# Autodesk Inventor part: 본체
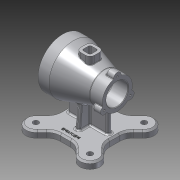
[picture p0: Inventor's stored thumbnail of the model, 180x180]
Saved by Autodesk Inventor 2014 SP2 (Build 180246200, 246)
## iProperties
Created: 2018-03
Part Number: 본체
Material: 알루미늄 6061
Document SubType Name: Modeling
Designer: 거성
Density: 2.71 g/cm^3
Appearance: 알루미늄 - 평지
Mass: 1030.73 g
Surface Area: 859.626 cm^2
Volume: 380.342 cm^3
Author: 거성
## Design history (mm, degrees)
sketch "스케치1"
  geometry: L1 (-50, 0)-(50, 0); L2 (-50, 36)-(-50, 45); L3 (-50, 45)-(-30, 45); L4 (-30, 45)-(27, 27.5); L5 (50, 27.5)-(50, 21); L6 (49, 20)-(23, 20); L7 (20, 23)-(20, 23); L8 (17, 26)-(-24, 26); L9 (-27, 29)-(-27, 32); L10 (-30, 35)-(-49, 35); L11 (27, 27.5)-(50, 27.5); L12 (-50, 36)-(-49, 35); L13 (49, 20)-(50, 21); A1 r 3 centre (-30, 32) between (-27, 32) and (-30, 35); A2 r 3 centre (-24, 29) between (-27, 29) and (-24, 26); A3 r 3 centre (17, 23) between (20, 23) and (17, 26); A4 r 3 centre (23, 23) between (20, 23) and (23, 20); 7 further points
  constraints: 26 end point, 10 point on line, 8 point on circle, 8 tangent, 7 parallel, 4 centre point, 3 equal radius, 2 perpendicular, 1 coincident, 1 horizontal, 1 midpoint
  dimensions: "d0" = 100 distance of L1.start L1.end; "d1" = 90 diameter of L3 L1; "d2" = 70 diameter of L10 L1; "d4" = 40 diameter of L6 L1; "d5" = 52 diameter of L8 L1; "d6" = 20 distance of L2.end L3.end; "d7" = 77 distance from line of L2 L4.end; "d8" = 100 distance between parallel lines of L5 L2; "d9" = 23 distance of point (-27, 35) point (-50, 35); "d10" = 47 distance of point (20, 26) point (-27, 26); "d11" = 55 diameter of L11 L1; "d12" = 49.99998 distance from line of L5 point (0, 0); "d13" = 3 radius of A1; "d14" = 1 distance of L2.start point (-50, 35); "d15" = 45 deg angle of L2 L12; "d16" = 1 distance of L6.start point (50, 20) (= d14); "d17" = 45 deg angle of L6 L13 (= d15)
revolve "회전1" sketch "스케치1" stored, may be unused: angle "d18" = 90 deg
node "작업 평면1"
sketch "스케치2"
  geometry: L1 (9.189, 45)-(-9.189, 45); L2 (-45, 9.189)-(-45, -9.189); L3 (44.289, 44.289)-(-44.289, -44.289); L4 (-45.7, 45.7)-(45.7, -45.7); L5 (115.887, 0)-(-115.887, 0); L6 (0, 0)-(84.957, -84.957); L7 (60.561, -35.105)-(52.322, -26.866); L8 (35.105, -60.561)-(26.866, -52.322); L9 (45, -9.189)-(45, 9.189); L10 (-9.189, -45)-(9.189, -45); L11 (35.105, 60.561)-(26.866, 52.322); L12 (60.561, 35.105)-(52.322, 26.866); L13 (0, 115.887)-(0, -115.887); L14 (-60.561, 35.105)-(-52.322, 26.866); L15 (-35.105, 60.561)-(-26.866, 52.322); L16 (-115.887, 0)-(115.887, 0); L17 (-35.105, -60.561)-(-26.866, -52.322); L18 (-60.561, -35.105)-(-52.322, -26.866); L19 (0, -115.887)-(0, 115.887); A1 r 70 centre (0, 0) between (49.497, -49.497) and (60.561, -35.105); A2 r 18.153 centre (49.497, -49.497) between (35.105, -60.561) and (60.561, -35.105); A3 r 18.153 centre (49.497, 49.497) between (60.561, 35.105) and (35.105, 60.561); A4 r 18.153 centre (-49.497, 49.497) between (-35.105, 60.561) and (-60.561, 35.105); A5 r 18.153 centre (-49.497, -49.497) between (-60.561, -35.105) and (-35.105, -60.561); A6 r 25 centre (70, -9.189) between (45, -9.189) and (52.322, -26.866); A7 r 25 centre (-70, 9.189) between (-45, 9.189) and (-52.322, 26.866); A8 r 25 centre (-70, -9.189) between (-52.322, -26.866) and (-45, -9.189); A9 r 25 centre (-9.189, -70) between (-9.189, -45) and (-26.866, -52.322); A10 r 25 centre (-9.189, 70) between (-26.866, 52.322) and (-9.189, 45); A11 r 25 centre (9.189, -70) between (26.866, -52.322) and (9.189, -45); A12 r 25 centre (70, 9.189) between (52.322, 26.866) and (45, 9.189); A13 r 25 centre (9.189, 70) between (9.189, 45) and (26.866, 52.322); 21 further points
  constraints: 38 end point, 27 point on circle, 17 point on line, 16 tangent, 13 centre point, 11 midpoint, 7 coincident, 5 parallel, 3 equal radius, 2 perpendicular, 1 collinear, 1 horizontal, 51 other
  dimensions: "d20" = 90 distance of L4.end L3.end; "d21" = 90 distance of L3.end L4.start; "d22" = 140 diameter of A1; "d23" = 45 deg angle of L6 L5 (derived); "d27" = 360 deg dimension on point (0, 0) L7.start (derived); "d29" = 90 distance between parallel lines of L2 L9; "d30" = 36 distance between parallel lines of L11 L12; "d33" = 25 radius of A6; "d34" = 25 radius of A7; "d35" = 90 distance between parallel lines of L10 L1 (derived); "d36" = 25 radius of A10; "d37" = 25 radius of A11; "d38" = 25 radius of A12
extrude "돌출1" join sketch "스케치2" distance "d39" = 12; taper "d40" = 0 deg
sketch "스케치3"
  geometry: L1 (9.189, 45)-(-9.189, 45) reference; L2 (-37, 0)-(37, 0); L3 (-37, 0)-(-33, 0); L4 (37, 0)-(33, 0); L5 (-33, 0)-(33, 0); L6 (-33, -4)-(33, -4); L7 (33, 4)-(-33, 4); A1 r 4 centre (-33, 0) between (-33, 4) and (-33, -4); A2 r 4 centre (33, 0) between (33, -4) and (33, 4); 3 further points
  constraints: 14 end point, 4 point on circle, 4 tangent, 2 centre point, 2 midpoint, 2 parallel, 2 point on line, 1 coincident, 1 collinear
  dimensions: "d41" = 74 distance of L2.start L2.end; "d42" = 4 distance of L2.start L3.end; "d43" = 4 distance of L2.end L4.end; "d44" = 8 distance between parallel lines of L6 L7
extrude "돌출2" join sketch "스케치3" stored distance "d45" = 12; taper "d46" = 0 deg
sketch "스케치4"
  geometry: L1 (-33, 4)-(33, 4) reference; L2 (33, -4)-(-33, -4) reference; L3 (-60.561, 35.105)-(-52.322, 26.866) reference; L4 (-45, 9.189)-(-45, -9.189) reference; L5 (-52.322, -26.866)-(-60.561, -35.105) reference; L6 (-35.105, -60.561)-(-26.866, -52.322) reference; L7 (-9.189, -45)-(9.189, -45) reference; L8 (26.866, -52.322)-(35.105, -60.561) reference; L9 (60.561, -35.105)-(52.322, -26.866) reference; L10 (45, -9.189)-(45, 9.189) reference; L11 (52.322, 26.866)-(60.561, 35.105) reference; L12 (35.105, 60.561)-(26.866, 52.322) reference; L13 (9.189, 45)-(-9.189, 45) reference; L14 (-26.866, 52.322)-(-35.105, 60.561) reference; L15 (0, -24)-(0, 24); L16 (0, -24)-(0, -20); L17 (0, 24)-(0, 20); L18 (0, -20)-(0, 20); L19 (4, -20)-(4, 20); L20 (-4, 20)-(-4, -20); A1 r 4 centre (-33, 0) between (-33, 4) and (-33, -4) reference; A2 r 4 centre (33, 0) between (33, -4) and (33, 4) reference; A3 r 25 centre (-70, 9.189) between (-45, 9.189) and (-52.322, 26.866) reference; A4 r 25 centre (-70, -9.189) between (-52.322, -26.866) and (-45, -9.189) reference; A5 r 18.153 centre (-49.497, -49.497) between (-60.561, -35.105) and (-35.105, -60.561) reference; A6 r 25 centre (-9.189, -70) between (-9.189, -45) and (-26.866, -52.322) reference; A7 r 25 centre (9.189, -70) between (26.866, -52.322) and (9.189, -45) reference; A8 r 18.153 centre (49.497, -49.497) between (35.105, -60.561) and (60.561, -35.105) reference; A9 r 25 centre (70, -9.189) between (45, -9.189) and (52.322, -26.866) reference; A10 r 25 centre (70, 9.189) between (52.322, 26.866) and (45, 9.189) reference; A11 r 18.153 centre (49.497, 49.497) between (60.561, 35.105) and (35.105, 60.561) reference; A12 r 25 centre (9.189, 70) between (9.189, 45) and (26.866, 52.322) reference; A13 r 25 centre (-9.189, 70) between (-26.866, 52.322) and (-9.189, 45) reference; A14 r 18.153 centre (-49.497, 49.497) between (-35.105, 60.561) and (-60.561, 35.105) reference; A15 r 4 centre (0, -20) between (-4, -20) and (4, -20); A16 r 4 centre (0, 20) between (4, 20) and (-4, 20); 3 further points
  constraints: 14 end point, 4 point on circle, 4 tangent, 2 centre point, 2 midpoint, 2 parallel, 2 point on line, 1 coincident, 1 perpendicular
  dimensions: "d47" = 48 distance of L15.start L15.end; "d48" = 4 distance of L15.start L16.end; "d49" = 4 distance of L15.end L17.end; "d50" = 8 diameter of A16
node "작업 평면2"
sketch "스케치5"
  geometry: L1 (-70.227, 0)-(-70.227, -24); L2 (-70.227, -24)-(-17.34, -19.373); L3 (-70, -35.105)-(-70, -26.866) reference; 2 further points
  constraints: 4 end point, 1 vertical, 2 other
  dimensions: "d52" = 24 distance of L1.start L1.end; "d53" = 95 deg angle of L3 L2
feature "리브1" sketch "스케치5" dims "d54" = 1, "d55" = 8, "d56" = 0, "d57" = 0, "d58" = 1, "d59" = 1
node "작업 평면3"
sketch "스케치6"
  geometry: L1 (0, 0)-(0, 27.5); C1 r 21 at (0, 0) reference; A1 r 27.5 centre (0, 0) between (6.943, 26.609) and (-6.943, 26.609); A2 r 7 centre (0, 27.5) between (6.943, 26.609) and (-6.943, 26.609); 1 further point
  constraints: 4 point on circle, 2 centre point, 2 coincident, 2 end point, 1 vertical, 1 vertical alignment, 2 other
  dimensions: "d62" = 7 radius of A2
extrude "돌출3" join sketch "스케치6" distance "d63" = 15; taper "d64" = 0 deg
node "작업 평면5"
sketch "스케치7"
  geometry: L1 (12.5, 12.5)-(-12.5, 12.5); L2 (-12.5, 12.5)-(-12.5, -12.5); L3 (-12.5, -12.5)-(12.5, -12.5); L4 (12.5, -12.5)-(12.5, 12.5); L5 (12.5, 12.5)-(-12.5, -12.5); L6 (-12.5, 12.5)-(12.5, -12.5); 1 further point
  constraints: 12 end point, 2 midpoint, 2 parallel, 1 horizontal, 1 perpendicular
  dimensions: "d66" = 25 distance of L3.end L2.end; "d67" = 25 distance of L2.end L1.end
extrude "돌출4" join sketch "스케치7" stored distance "d68" = 15; taper "d69" = 0 deg
sketch "스케치8"
  geometry: L1 (-4.5, 7.5)-(4.5, 7.5); L2 (7.5, 4.5)-(7.5, -4.5); L3 (4.5, -7.5)-(-4.5, -7.5); L4 (-7.5, -4.5)-(-7.5, 4.5); L5 (-7.5, 7.5)-(7.5, -7.5); L6 (7.5, 7.5)-(-7.5, -7.5); A1 r 3 centre (4.5, 4.5) between (7.5, 4.5) and (4.5, 7.5); A2 r 3 centre (-4.5, 4.5) between (-4.5, 7.5) and (-7.5, 4.5); A3 r 3 centre (-4.5, -4.5) between (-7.5, -4.5) and (-4.5, -7.5); A4 r 3 centre (4.5, -4.5) between (4.5, -7.5) and (7.5, -4.5); 1 further point
  constraints: 12 end point, 8 point on circle, 8 point on line, 8 tangent, 4 centre point, 3 equal radius, 2 midpoint, 2 parallel, 1 horizontal, 1 perpendicular
  dimensions: "d70" = 15 distance of L5.end L6.end; "d71" = 15 distance of L6.start L5.end; "d72" = 3 radius of A1
extrude "돌출5" cut sketch "스케치8" stored distance "d73" = 15; taper "d74" = 0 deg
fillet "모깎기1" dims "d75" = 8
fillet "모깎기2" dims "d76" = 1
fillet "모깎기3" dims "d77" = 3
fillet "모깎기4" dims "d78" = 1
sketch "스케치9" dims "d79" = 80
  geometry: L1 (0, 0)-(0, 40); C1 r 45 at (0, 0) reference; 1 further point
  constraints: 2 coincident, 2 end point, 1 vertical, 1 vertical alignment, 2 other
hole "구멍1" sketch "스케치9" at (0, 40) diameter "d80" = 4.917; stored, may be unused: countersink angle "d84" = 90 deg, drill point angle "d86" = 118 deg; dims "d81" = 9, "d82" = 4, "d83" = 2, "d85" = 11
sketch "스케치10"
  geometry: C1 r 21 at (0, -27.5) reference; A1 r 27.5 centre (0, -27.5) between (-7.718, -1.105) and (7.718, -1.105) reference; A2 r 1 centre (7.999, -0.145) between (6.999, -0.127) and (7.718, -1.105) reference; A3 r 7 centre (0, 0) between (6.999, -0.127) and (-6.999, -0.127) reference; A4 r 1 centre (-7.999, -0.145) between (-7.718, -1.105) and (-6.999, -0.127) reference
hole "구멍2" diameter "d92" = 3.242; stored, may be unused: countersink angle "d96" = 90 deg, drill point angle "d98" = 118 deg; dims "d90" = 10, "d91" = 10, "d93" = 9, "d94" = 4, "d95" = 2, "d97" = 11
sketch "스케치11"
  geometry: 2 further points
  constraints: 1 vertical alignment, 1 other
  dimensions: "d102" = 35 distance of point (0, 0) point (0, -35)
feature "엠보싱1" sketch "스케치11" dims "d0" = 100, "d1" = 90, "d2" = 70, "d4" = 40, "d5" = 52, "d6" = 20, "d7" = 77, "d8" = 100, "d9" = 23, "d10" = 47, "d11" = 55, "d12" = 49.99998, "d13" = 3, "d14" = 1, "d15" = 45 deg, "d16" = 1 (= d14), "d17" = 45 deg (= d15), "d103" = 0.5, "d104" = 0
fillet "모깎기5" dims "d105" = 3
fillet "모깎기6" dims "d106" = 3
fillet "모깎기7" dims "d107" = 3
fillet "모깎기8" dims "d108" = 3
fillet "모깎기9" dims "d109" = 3
chamfer "모따기1" distance "d110" = 3; stored, may be unused: second distance "d111" = 2, angle "d112" = 45 deg
chamfer "모따기2" distance "d113" = 3; stored, may be unused: second distance "d114" = 2, angle "d115" = 45 deg
chamfer "모따기3" distance "d116" = 3; stored, may be unused: second distance "d117" = 2, angle "d118" = 45 deg
hole "구멍3" diameter "d121" = 10; stored, may be unused: countersink angle "d125" = 90 deg, drill point angle "d127" = 0 deg; dims "d119" = 10, "d120" = 10, "d122" = 9, "d123" = 4, "d124" = 2, "d126" = 11
hole "구멍4" diameter "d130" = 10; stored, may be unused: countersink angle "d134" = 90 deg, drill point angle "d136" = 0 deg; dims "d128" = 10, "d129" = 10, "d131" = 9, "d132" = 4, "d133" = 2, "d135" = 11
hole "구멍5" diameter "d139" = 10; stored, may be unused: countersink angle "d143" = 90 deg, drill point angle "d145" = 0 deg; dims "d137" = 10, "d138" = 10, "d140" = 9, "d141" = 4, "d142" = 2, "d144" = 11
hole "구멍6" diameter "d148" = 10; stored, may be unused: countersink angle "d152" = 90 deg, drill point angle "d154" = 0 deg; dims "d146" = 10, "d147" = 10, "d149" = 9, "d150" = 4, "d151" = 2, "d153" = 11
node "솔리드1"
mirror "대칭1"
pattern_circular "원형 패턴1" dims angle "d88" = 360 deg
pattern_circular "원형 패턴2" dims "d100" = 360 deg
node "작업 평면4"
other parameters: "d19" = -82, "d24" = 36, "d51" = 0, "d60" = 0, "d61" = 14, "d65" = 45
